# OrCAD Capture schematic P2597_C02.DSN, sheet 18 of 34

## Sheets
18 16_IO Expansion Connector: size Custom
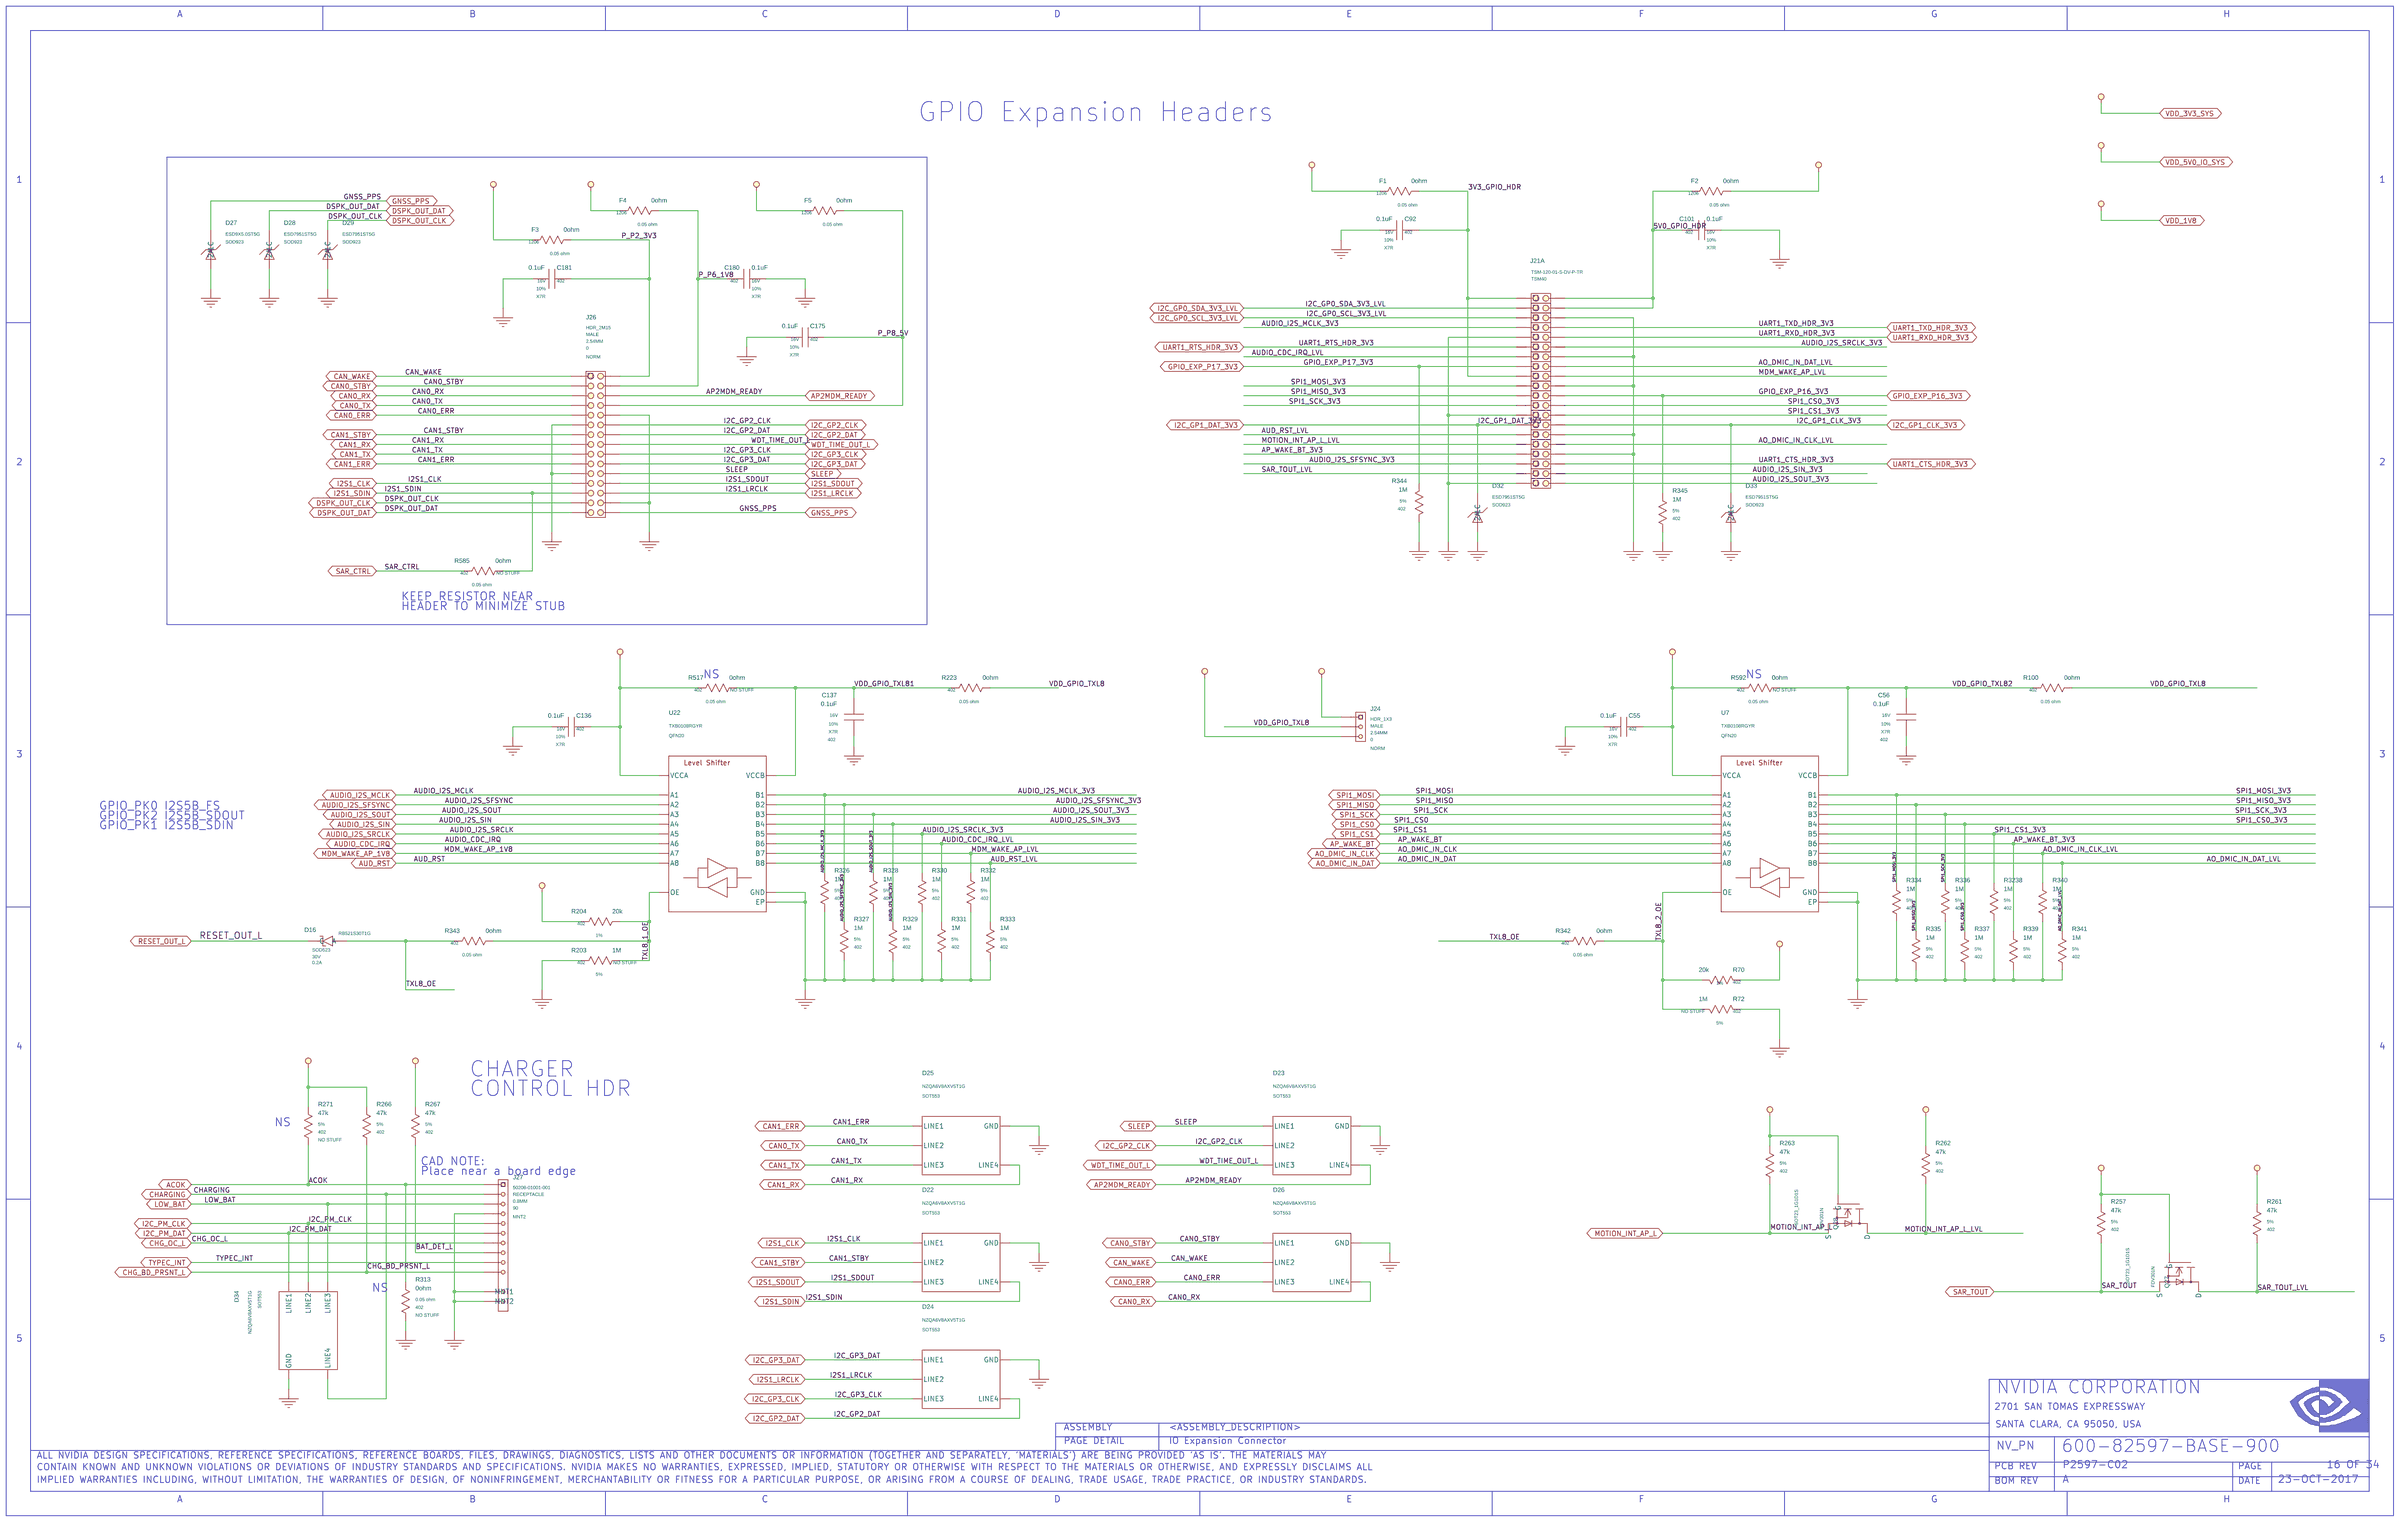
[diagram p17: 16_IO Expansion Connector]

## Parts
C55  0.1uF  [402]
C56  0.1uF  [402]
C92  0.1uF  [402]
C101  0.1uF  [402]
C136  0.1uF  [402]
C137  0.1uF  [402]
C175  0.1uF  [402]
C180  0.1uF  [402]
C181  0.1uF  [402]
D16  D_SCHOTTKY  [DIODE_SMD_SOD523_B]
D22  D_ESD  [SOT553]
D23  D_ESD  [SOT553]
D24  D_ESD  [SOT553]
D25  D_ESD  [SOT553]
D26  D_ESD  [SOT553]
D27  D_ESD  [DIODE_SMD_SOD923]
D28  D_ESD  [DIODE_SMD_SOD923]
D29  D_ESD  [DIODE_SMD_SOD923]
D32  D_ESD  [DIODE_SMD_SOD923]
D33  D_ESD  [DIODE_SMD_SOD923]
D34  D_ESD  [SOT553]
F1  0ohm  [1206]
F2  0ohm  [1206]
F3  0ohm  [1206]
F4  0ohm  [1206]
F5  0ohm  [1206]
J21  HDR_2X20  [CON_TSM_002X020_SMD_ST_M_P025]  (sections A,B,C,D,E,F,G,H,I,J,K,L,M,N,O,P,Q,R,S,T)
J24  HDR_1X3  [CON_HDR_001X003_TH_ST_M_P025_C]
J26  HDR_2X15  [CON_HDR_002X015_TH_ST_M_P025]
J27  HDR_1X10  [CON_MISC_010_SMD_RA_F_P008_WTB]
Q27  Q_FET_N_ENH  [SOT23]
Q28  Q_FET_N_ENH  [SOT23]
R70  20k  [402]
R72  1M  [402]
R100  0ohm  [402]
R203  1M  [402]
R204  20k  [402]
R223  0ohm  [402]
R257  47k  [402]
R261  47k  [402]
R262  47k  [402]
R263  47k  [402]
R266  47k  [402]
R267  47k  [402]
R271  47k  [402]
R313  0ohm  [402]
R326  1M  [402]
R327  1M  [402]
R328  1M  [402]
R329  1M  [402]
R330  1M  [402]
R331  1M  [402]
R332  1M  [402]
R333  1M  [402]
R334  1M  [402]
R335  1M  [402]
R336  1M  [402]
R337  1M  [402]
R339  1M  [402]
R340  1M  [402]
R341  1M  [402]
R342  0ohm  [402]
R343  0ohm  [402]
R344  1M  [402]
R345  1M  [402]
R517  0ohm  [402]
R585  0ohm  [402]
R592  0ohm  [402]
R3238  1M  [402]
U7  U_LEVSHFT_TXB0108  [QFN020R_P050_0045X0035_T031X021_VIAS]
U22  U_LEVSHFT_TXB0108  [QFN020R_P050_0045X0035_T031X021_VIAS]

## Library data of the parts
C55 = C#1: ASSEMBLY: GPIO_HDR; CDS_LIB: discrete; CDS_PART_NAME: C_0402-0.1UF,X7R,10%,16V,036-0014-000; CDS_PHYS_PART_NAME: C_0402-0.1UF,X7R,10%,16V,036-0014-000-0.1UF,036-0014-000; CDS_SEC: 1; CHIPS_PART_NAME: C; DEVICE_TYPENAME: C_0402-01UFX7R1016V036-0014-000-01UF036-0014-000; DRAWING: @P2597_C02_LIB.P2597_C02(SCH_1):PAGE16; ESL: N/A; ESR: N/A; MAT: X7R; MAX_VOLTAGE: 16V; NV_PN: 036-0014-000; PATH: I137; PHYS_PAGE: 16; ROT: 2; SEC: 1; SIGNAL_MODEL: nv_cap; TOL: 10%; VER: 2; XY: (-3850,3900)
C56 = C: ASSEMBLY: GPIO_HDR; CDS_LIB: discrete; CDS_PART_NAME: C_0402-0.1UF,X7R,10%,16V,036-0014-000; CDS_PHYS_PART_NAME: C_0402-0.1UF,X7R,10%,16V,036-0014-000-0.1UF,036-0014-000; CDS_SEC: 1; DEVICE_TYPENAME: C_0402-01UFX7R1016V036-0014-000-01UF036-0014-000; DRAWING: @P2597_C02_LIB.P2597_C02(SCH_1):PAGE16; ESL: N/A; ESR: N/A; MAT: X7R; MAX_VOLTAGE: 16V; NV_PN: 036-0014-000; PATH: I139; PHYS_PAGE: 16; ROT: 2; SEC: 1; SIGNAL_MODEL: nv_cap; TOL: 10%; VER: 1; XY: (-2400,3950)
C92 = C#1: ASSEMBLY: GPIO_HDR; CDS_LIB: discrete; CDS_PART_NAME: C_0402-0.1UF,X7R,10%,16V,036-0014-000; CDS_PHYS_PART_NAME: C_0402-0.1UF,X7R,10%,16V,036-0014-000-0.1UF,036-0014-000; CDS_SEC: 1; CHIPS_PART_NAME: C; DEVICE_TYPENAME: C_0402-01UFX7R1016V036-0014-000-01UF036-0014-000; DRAWING: @P2597_C02_LIB.P2597_C02(SCH_1):PAGE16; ESL: N/A; ESR: N/A; MAT: X7R; MAX_VOLTAGE: 16V; NV_PN: 036-0014-000; PATH: I33; PHYS_PAGE: 16; ROT: 2; SEC: 1; SIGNAL_MODEL: nv_cap; TOL: 10%; VER: 2; XY: (-5000,6450)
C101 = C#1: ASSEMBLY: GPIO_HDR; CDS_LIB: discrete; CDS_PART_NAME: C_0402-0.1UF,X7R,10%,16V,036-0014-000; CDS_PHYS_PART_NAME: C_0402-0.1UF,X7R,10%,16V,036-0014-000-0.1UF,036-0014-000; CDS_SEC: 1; CHIPS_PART_NAME: C; DEVICE_TYPENAME: C_0402-01UFX7R1016V036-0014-000-01UF036-0014-000; DRAWING: @P2597_C02_LIB.P2597_C02(SCH_1):PAGE16; ESL: N/A; ESR: N/A; MAT: X7R; MAX_VOLTAGE: 16V; NV_PN: 036-0014-000; PATH: I41; PHYS_PAGE: 16; ROT: 0; SEC: 1; SIGNAL_MODEL: nv_cap; TOL: 10%; VER: 2; XY: (-3450,6450)
C136 = C#1: ASSEMBLY: GPIO_HDR; CDS_LIB: discrete; CDS_PART_NAME: C_0402-0.1UF,X7R,10%,16V,036-0014-000; CDS_PHYS_PART_NAME: C_0402-0.1UF,X7R,10%,16V,036-0014-000-0.1UF,036-0014-000; CDS_SEC: 1; CHIPS_PART_NAME: C; DEVICE_TYPENAME: C_0402-01UFX7R1016V036-0014-000-01UF036-0014-000; DRAWING: @P2597_C02_LIB.P2597_C02(SCH_1):PAGE16; ESL: N/A; ESR: N/A; MAT: X7R; MAX_VOLTAGE: 16V; NV_PN: 036-0014-000; PATH: I118; PHYS_PAGE: 16; ROT: 2; SEC: 1; SIGNAL_MODEL: nv_cap; TOL: 10%; VER: 2; XY: (-9250,3900)
C137 = C: ASSEMBLY: GPIO_HDR; CDS_LIB: discrete; CDS_PART_NAME: C_0402-0.1UF,X7R,10%,16V,036-0014-000; CDS_PHYS_PART_NAME: C_0402-0.1UF,X7R,10%,16V,036-0014-000-0.1UF,036-0014-000; CDS_SEC: 1; DEVICE_TYPENAME: C_0402-01UFX7R1016V036-0014-000-01UF036-0014-000; DRAWING: @P2597_C02_LIB.P2597_C02(SCH_1):PAGE16; ESL: N/A; ESR: N/A; MAT: X7R; MAX_VOLTAGE: 16V; NV_PN: 036-0014-000; PATH: I120; PHYS_PAGE: 16; ROT: 2; SEC: 1; SIGNAL_MODEL: nv_cap; TOL: 10%; VER: 1; XY: (-7800,3950)
C175 = C#1: ASSEMBLY: GPIO_HDR; CDS_LIB: discrete; CDS_PART_NAME: C_0402-0.1UF,X7R,10%,16V,036-0014-000; CDS_PHYS_PART_NAME: C_0402-0.1UF,X7R,10%,16V,036-0014-000-0.1UF,036-0014-000; CDS_SEC: 1; CHIPS_PART_NAME: C; DEVICE_TYPENAME: C_0402-01UFX7R1016V036-0014-000-01UF036-0014-000; DRAWING: @P2597_C02_LIB.P2597_C02(SCH_1):PAGE16; ESL: N/A; ESR: N/A; MAT: X7R; MAX_VOLTAGE: 16V; NV_PN: 036-0014-000; PATH: I363; PHYS_PAGE: 16; ROT: 2; SEC: 1; SIGNAL_MODEL: nv_cap; TOL: 10%; VER: 2; XY: (-8050,5900)
C180 = C#1: ASSEMBLY: GPIO_HDR; CDS_LIB: discrete; CDS_PART_NAME: C_0402-0.1UF,X7R,10%,16V,036-0014-000; CDS_PHYS_PART_NAME: C_0402-0.1UF,X7R,10%,16V,036-0014-000-0.1UF,036-0014-000; CDS_SEC: 1; CHIPS_PART_NAME: C; DEVICE_TYPENAME: C_0402-01UFX7R1016V036-0014-000-01UF036-0014-000; DRAWING: @P2597_C02_LIB.P2597_C02(SCH_1):PAGE16; ESL: N/A; ESR: N/A; MAT: X7R; MAX_VOLTAGE: 16V; NV_PN: 036-0014-000; PATH: I271; PHYS_PAGE: 16; ROT: 0; SEC: 1; SIGNAL_MODEL: nv_cap; TOL: 10%; VER: 2; XY: (-8350,6200)
C181 = C#1: ASSEMBLY: GPIO_HDR; CDS_LIB: discrete; CDS_PART_NAME: C_0402-0.1UF,X7R,10%,16V,036-0014-000; CDS_PHYS_PART_NAME: C_0402-0.1UF,X7R,10%,16V,036-0014-000-0.1UF,036-0014-000; CDS_SEC: 1; CHIPS_PART_NAME: C; DEVICE_TYPENAME: C_0402-01UFX7R1016V036-0014-000-01UF036-0014-000; DRAWING: @P2597_C02_LIB.P2597_C02(SCH_1):PAGE16; ESL: N/A; ESR: N/A; MAT: X7R; MAX_VOLTAGE: 16V; NV_PN: 036-0014-000; PATH: I266; PHYS_PAGE: 16; ROT: 2; SEC: 1; SIGNAL_MODEL: nv_cap; TOL: 10%; VER: 2; XY: (-9350,6200)
D16 = D_SCHOTTKY: ASSEMBLY: GPIO_HDR; CDS_LIB: discrete; CDS_PART_NAME: D_SCHOTTKY_SOD523-RB521S30T1G,SINGLE,30V,1A,0.5V@0.2A,0.2A,090-0102-000; CDS_PHYS_PART_NAME: D_SCHOTTKY_SOD523-RB521S30T1G,SINGLE,30V,1A,0.5V@0.2A,0.2A,090-0102-000-090-0102-000; CDS_SEC: 1; CONFIGURATION: Single; CONTINUOUS_CURRENT: 0.2A; DEVICE_TYPENAME: D_SCHOTTKY_SOD523-RB521S30T1GSINGLE30V1A05V02A02A090-0102-000-090-0102-000; DRAWING: @P2597_C02_LIB.P2597_C02(SCH_1):PAGE16; FORWARD_VOLTAGE: 0.5V@0.2A; MAX_CURRENT: 1A; MAX_VOLTAGE: 30V; NV_NAME: RB521S30T1G; NV_PN: 090-0102-000; PACK_TYPE: SOD523; PATH: I455; PHYS_PAGE: 16; ROT: 0; SEC: 1; SEC_TYPE: SOD523; VER: 1; XY: (-10500,2800)
D22 = D_ESD#3: ASSEMBLY: GPIO_HDR; BREAKDOWN_VOLTAGE_MIN_TYP: 6.47V; CAPACITANCE_MAX_TYP: 9.5pF; CDS_LIB: discrete; CDS_PART_NAME: D_ESD_SOT553-NZQA6V8AXV5T1G,4 LINE,UNI-DIRECTIONAL,4.3V,1UA,6.47V,13V@1.6A,9.5PF,091-0083-000; CDS_PHYS_PART_NAME: D_ESD_SOT553-NZQA6V8AXV5T1G,4 LINE,UNI-DIRECTIONAL,4.3V,1UA,6.47V,13V@1.6A,9.5PF,091-0083-000-091-0083-000; CDS_SEC: 1; CLAMPING_VOLTAGE: 13V@1.6A; CONFIGURATION: 4 Line; DEVICE_TYPENAME: D_ESD_SOT553-NZQA6V8AXV5T1G4LINEUNI-DIRECTIONAL43V1UA647V13V16A95PF091-0083-000-091-0083-000; DRAWING: @P2597_C02_LIB.P2597_C02(SCH_1):PAGE16; MAX_REVERSE_LEAKAGE_CURRENT: 1uA; MAX_REVERSE_VOLTAGE: 4.3V; NV_NAME: NZQA6V8AXV5T1G; NV_PN: 091-0083-000; PATH: I493; PHYS_PAGE: 16; POLARITY: Uni-Directional; ROT: 0; SEC: 1; VER: 6; XY: (-7250,1150)
D23 = D_ESD#3: ASSEMBLY: GPIO_HDR; BREAKDOWN_VOLTAGE_MIN_TYP: 6.47V; CAPACITANCE_MAX_TYP: 9.5pF; CDS_LIB: discrete; CDS_PART_NAME: D_ESD_SOT553-NZQA6V8AXV5T1G,4 LINE,UNI-DIRECTIONAL,4.3V,1UA,6.47V,13V@1.6A,9.5PF,091-0083-000; CDS_PHYS_PART_NAME: D_ESD_SOT553-NZQA6V8AXV5T1G,4 LINE,UNI-DIRECTIONAL,4.3V,1UA,6.47V,13V@1.6A,9.5PF,091-0083-000-091-0083-000; CDS_SEC: 1; CLAMPING_VOLTAGE: 13V@1.6A; CONFIGURATION: 4 Line; DEVICE_TYPENAME: D_ESD_SOT553-NZQA6V8AXV5T1G4LINEUNI-DIRECTIONAL43V1UA647V13V16A95PF091-0083-000-091-0083-000; DRAWING: @P2597_C02_LIB.P2597_C02(SCH_1):PAGE16; MAX_REVERSE_LEAKAGE_CURRENT: 1uA; MAX_REVERSE_VOLTAGE: 4.3V; NV_NAME: NZQA6V8AXV5T1G; NV_PN: 091-0083-000; PATH: I494; PHYS_PAGE: 16; POLARITY: Uni-Directional; ROT: 0; SEC: 1; VER: 6; XY: (-5450,1750)
D24 = D_ESD#3: ASSEMBLY: GPIO_HDR; BREAKDOWN_VOLTAGE_MIN_TYP: 6.47V; CAPACITANCE_MAX_TYP: 9.5pF; CDS_LIB: discrete; CDS_PART_NAME: D_ESD_SOT553-NZQA6V8AXV5T1G,4 LINE,UNI-DIRECTIONAL,4.3V,1UA,6.47V,13V@1.6A,9.5PF,091-0083-000; CDS_PHYS_PART_NAME: D_ESD_SOT553-NZQA6V8AXV5T1G,4 LINE,UNI-DIRECTIONAL,4.3V,1UA,6.47V,13V@1.6A,9.5PF,091-0083-000-091-0083-000; CDS_SEC: 1; CLAMPING_VOLTAGE: 13V@1.6A; CONFIGURATION: 4 Line; DEVICE_TYPENAME: D_ESD_SOT553-NZQA6V8AXV5T1G4LINEUNI-DIRECTIONAL43V1UA647V13V16A95PF091-0083-000-091-0083-000; DRAWING: @P2597_C02_LIB.P2597_C02(SCH_1):PAGE16; MAX_REVERSE_LEAKAGE_CURRENT: 1uA; MAX_REVERSE_VOLTAGE: 4.3V; NV_NAME: NZQA6V8AXV5T1G; NV_PN: 091-0083-000; PATH: I492; PHYS_PAGE: 16; POLARITY: Uni-Directional; ROT: 0; SEC: 1; VER: 6; XY: (-7250,550)
D25 = D_ESD#3: ASSEMBLY: GPIO_HDR; BREAKDOWN_VOLTAGE_MIN_TYP: 6.47V; CAPACITANCE_MAX_TYP: 9.5pF; CDS_LIB: discrete; CDS_PART_NAME: D_ESD_SOT553-NZQA6V8AXV5T1G,4 LINE,UNI-DIRECTIONAL,4.3V,1UA,6.47V,13V@1.6A,9.5PF,091-0083-000; CDS_PHYS_PART_NAME: D_ESD_SOT553-NZQA6V8AXV5T1G,4 LINE,UNI-DIRECTIONAL,4.3V,1UA,6.47V,13V@1.6A,9.5PF,091-0083-000-091-0083-000; CDS_SEC: 1; CLAMPING_VOLTAGE: 13V@1.6A; CONFIGURATION: 4 Line; DEVICE_TYPENAME: D_ESD_SOT553-NZQA6V8AXV5T1G4LINEUNI-DIRECTIONAL43V1UA647V13V16A95PF091-0083-000-091-0083-000; DRAWING: @P2597_C02_LIB.P2597_C02(SCH_1):PAGE16; MAX_REVERSE_LEAKAGE_CURRENT: 1uA; MAX_REVERSE_VOLTAGE: 4.3V; NV_NAME: NZQA6V8AXV5T1G; NV_PN: 091-0083-000; PATH: I496; PHYS_PAGE: 16; POLARITY: Uni-Directional; ROT: 0; SEC: 1; VER: 6; XY: (-7250,1750)
D26 = D_ESD#3: ASSEMBLY: GPIO_HDR; BREAKDOWN_VOLTAGE_MIN_TYP: 6.47V; CAPACITANCE_MAX_TYP: 9.5pF; CDS_LIB: discrete; CDS_PART_NAME: D_ESD_SOT553-NZQA6V8AXV5T1G,4 LINE,UNI-DIRECTIONAL,4.3V,1UA,6.47V,13V@1.6A,9.5PF,091-0083-000; CDS_PHYS_PART_NAME: D_ESD_SOT553-NZQA6V8AXV5T1G,4 LINE,UNI-DIRECTIONAL,4.3V,1UA,6.47V,13V@1.6A,9.5PF,091-0083-000-091-0083-000; CDS_SEC: 1; CLAMPING_VOLTAGE: 13V@1.6A; CONFIGURATION: 4 Line; DEVICE_TYPENAME: D_ESD_SOT553-NZQA6V8AXV5T1G4LINEUNI-DIRECTIONAL43V1UA647V13V16A95PF091-0083-000-091-0083-000; DRAWING: @P2597_C02_LIB.P2597_C02(SCH_1):PAGE16; MAX_REVERSE_LEAKAGE_CURRENT: 1uA; MAX_REVERSE_VOLTAGE: 4.3V; NV_NAME: NZQA6V8AXV5T1G; NV_PN: 091-0083-000; PATH: I499; PHYS_PAGE: 16; POLARITY: Uni-Directional; ROT: 0; SEC: 1; VER: 6; XY: (-5450,1150)
D27 = D_ESD#1: ASSEMBLY: GPIO_HDR; BREAKDOWN_VOLTAGE_MIN_TYP: 6.2V; CAPACITANCE_MAX_TYP: 65pF; CDS_LIB: discrete; CDS_PART_NAME: D_ESD_SOD923-ESD9X5.0ST5G,1 LINE,UNI-DIRECTIONAL,5V,1UA,6.2V,12.3V@8.7A,65PF,090-0134-000; CDS_PHYS_PART_NAME: D_ESD_SOD923-ESD9X5.0ST5G,1 LINE,UNI-DIRECTIONAL,5V,1UA,6.2V,12.3V@8.7A,65PF,090-0134-000-090-0134-000; CDS_SEC: 1; CLAMPING_VOLTAGE: 12.3V@8.7A; CONFIGURATION: 1 Line; CONTINUOUS_CURRENT: -1A; DEVICE_TYPENAME: D_ESD_SOD923-ESD9X50ST5G1LINEUNI-DIRECTIONAL5V1UA62V123V87A65PF090-0134-000-090-0134-000; DRAWING: @P2597_C02_LIB.P2597_C02(SCH_1):PAGE16; FORWARD_VOLTAGE: [ ]@-9.999A; MAX_CURRENT: [ ]; MAX_REVERSE_LEAKAGE_CURRENT: 1uA; MAX_REVERSE_VOLTAGE: 5V; MAX_VOLTAGE: 5V; NV_NAME: ESD9X5.0ST5G; NV_PN: 090-0134-000; PACK_TYPE: SOD923; PATH: I533; PHYS_PAGE: 16; POLARITY: Uni-Directional; ROT: 0; SEC: 1; VER: 5; XY: (-11100,6350)
D28 = D_ESD#1: ASSEMBLY: GPIO_HDR; BREAKDOWN_VOLTAGE_MIN_TYP: 5.4V; CAPACITANCE_MAX_TYP: 0.9pF; CDS_LIB: discrete; CDS_PART_NAME: D_ESD_SOD923-ESD7951ST5G,1 LINE,BI-DIRECTIONAL,5V,1UA,5.4V,12.9V@1A,0.9PF,091-0074-000; CDS_PHYS_PART_NAME: D_ESD_SOD923-ESD7951ST5G,1 LINE,BI-DIRECTIONAL,5V,1UA,5.4V,12.9V@1A,0.9PF,091-0074-000-091-0074-000; CDS_SEC: 1; CLAMPING_VOLTAGE: 12.9V@1A; CONFIGURATION: 1 Line; CONTINUOUS_CURRENT: -1A; DEVICE_TYPENAME: D_ESD_SOD923-ESD7951ST5G1LINEBI-DIRECTIONAL5V1UA54V129V1A09PF091-0074-000-091-0074-000; DRAWING: @P2597_C02_LIB.P2597_C02(SCH_1):PAGE16; FORWARD_VOLTAGE: [ ]@-9.999A; MAX_CURRENT: [ ]; MAX_REVERSE_LEAKAGE_CURRENT: 1uA; MAX_REVERSE_VOLTAGE: 5V; MAX_VOLTAGE: 5V; NV_NAME: ESD7951ST5G; NV_PN: 091-0074-000; PACK_TYPE: SOD923; PATH: I500; PHYS_PAGE: 16; POLARITY: Bi-Directional; ROT: 0; SEC: 1; VER: 5; XY: (-10800,6350)
D29 = D_ESD#1: ASSEMBLY: GPIO_HDR; BREAKDOWN_VOLTAGE_MIN_TYP: 5.4V; CAPACITANCE_MAX_TYP: 0.9pF; CDS_LIB: discrete; CDS_PART_NAME: D_ESD_SOD923-ESD7951ST5G,1 LINE,BI-DIRECTIONAL,5V,1UA,5.4V,12.9V@1A,0.9PF,091-0074-000; CDS_PHYS_PART_NAME: D_ESD_SOD923-ESD7951ST5G,1 LINE,BI-DIRECTIONAL,5V,1UA,5.4V,12.9V@1A,0.9PF,091-0074-000-091-0074-000; CDS_SEC: 1; CLAMPING_VOLTAGE: 12.9V@1A; CONFIGURATION: 1 Line; CONTINUOUS_CURRENT: -1A; DEVICE_TYPENAME: D_ESD_SOD923-ESD7951ST5G1LINEBI-DIRECTIONAL5V1UA54V129V1A09PF091-0074-000-091-0074-000; DRAWING: @P2597_C02_LIB.P2597_C02(SCH_1):PAGE16; FORWARD_VOLTAGE: [ ]@-9.999A; MAX_CURRENT: [ ]; MAX_REVERSE_LEAKAGE_CURRENT: 1uA; MAX_REVERSE_VOLTAGE: 5V; MAX_VOLTAGE: 5V; NV_NAME: ESD7951ST5G; NV_PN: 091-0074-000; PACK_TYPE: SOD923; PATH: I502; PHYS_PAGE: 16; POLARITY: Bi-Directional; ROT: 0; SEC: 1; VER: 5; XY: (-10500,6350)
D32 = D_ESD#1: ASSEMBLY: GPIO_HDR; BREAKDOWN_VOLTAGE_MIN_TYP: 5.4V; CAPACITANCE_MAX_TYP: 0.9pF; CDS_LIB: discrete; CDS_PART_NAME: D_ESD_SOD923-ESD7951ST5G,1 LINE,BI-DIRECTIONAL,5V,1UA,5.4V,12.9V@1A,0.9PF,091-0074-000; CDS_PHYS_PART_NAME: D_ESD_SOD923-ESD7951ST5G,1 LINE,BI-DIRECTIONAL,5V,1UA,5.4V,12.9V@1A,0.9PF,091-0074-000-091-0074-000; CDS_SEC: 1; CLAMPING_VOLTAGE: 12.9V@1A; CONFIGURATION: 1 Line; CONTINUOUS_CURRENT: -1A; DEVICE_TYPENAME: D_ESD_SOD923-ESD7951ST5G1LINEBI-DIRECTIONAL5V1UA54V129V1A09PF091-0074-000-091-0074-000; DRAWING: @P2597_C02_LIB.P2597_C02(SCH_1):PAGE16; FORWARD_VOLTAGE: [ ]@-9.999A; MAX_CURRENT: [ ]; MAX_REVERSE_LEAKAGE_CURRENT: 1uA; MAX_REVERSE_VOLTAGE: 5V; MAX_VOLTAGE: 5V; NV_NAME: ESD7951ST5G; NV_PN: 091-0074-000; PACK_TYPE: SOD923; PATH: I506; PHYS_PAGE: 16; POLARITY: Bi-Directional; ROT: 0; SEC: 1; SEC_TYPE: SOD923; VER: 5; XY: (-4600,5000)
D33 = D_ESD#1: ASSEMBLY: GPIO_HDR; BREAKDOWN_VOLTAGE_MIN_TYP: 5.4V; CAPACITANCE_MAX_TYP: 0.9pF; CDS_LIB: discrete; CDS_PART_NAME: D_ESD_SOD923-ESD7951ST5G,1 LINE,BI-DIRECTIONAL,5V,1UA,5.4V,12.9V@1A,0.9PF,091-0074-000; CDS_PHYS_PART_NAME: D_ESD_SOD923-ESD7951ST5G,1 LINE,BI-DIRECTIONAL,5V,1UA,5.4V,12.9V@1A,0.9PF,091-0074-000-091-0074-000; CDS_SEC: 1; CLAMPING_VOLTAGE: 12.9V@1A; CONFIGURATION: 1 Line; CONTINUOUS_CURRENT: -1A; DEVICE_TYPENAME: D_ESD_SOD923-ESD7951ST5G1LINEBI-DIRECTIONAL5V1UA54V129V1A09PF091-0074-000-091-0074-000; DRAWING: @P2597_C02_LIB.P2597_C02(SCH_1):PAGE16; FORWARD_VOLTAGE: [ ]@-9.999A; MAX_CURRENT: [ ]; MAX_REVERSE_LEAKAGE_CURRENT: 1uA; MAX_REVERSE_VOLTAGE: 5V; MAX_VOLTAGE: 5V; NV_NAME: ESD7951ST5G; NV_PN: 091-0074-000; PACK_TYPE: SOD923; PATH: I504; PHYS_PAGE: 16; POLARITY: Bi-Directional; ROT: 0; SEC: 1; SEC_TYPE: SOD923; VER: 5; XY: (-3300,5000)
D34 = D_ESD#3: ASSEMBLY: GPIO_HDR; BREAKDOWN_VOLTAGE_MIN_TYP: 6.47V; CAPACITANCE_MAX_TYP: 9.5pF; CDS_LIB: discrete; CDS_PART_NAME: D_ESD_SOT553-NZQA6V8AXV5T1G,4 LINE,UNI-DIRECTIONAL,4.3V,1UA,6.47V,13V@1.6A,9.5PF,091-0083-000; CDS_PHYS_PART_NAME: D_ESD_SOT553-NZQA6V8AXV5T1G,4 LINE,UNI-DIRECTIONAL,4.3V,1UA,6.47V,13V@1.6A,9.5PF,091-0083-000-091-0083-000; CDS_SEC: 1; CLAMPING_VOLTAGE: 13V@1.6A; CONFIGURATION: 4 Line; DEVICE_TYPENAME: D_ESD_SOT553-NZQA6V8AXV5T1G4LINEUNI-DIRECTIONAL43V1UA647V13V16A95PF091-0083-000-091-0083-000; DRAWING: @P2597_C02_LIB.P2597_C02(SCH_1):PAGE16; MAX_REVERSE_LEAKAGE_CURRENT: 1uA; MAX_REVERSE_VOLTAGE: 4.3V; NV_NAME: NZQA6V8AXV5T1G; NV_PN: 091-0083-000; PATH: I508; PHYS_PAGE: 16; POLARITY: Uni-Directional; ROT: 3; SEC: 1; VER: 6; XY: (-10600,800)
F1 = R: ASSEMBLY: GPIO_HDR; CDS_LIB: discrete; CDS_PART_NAME: R_1206-0OHM,0.05 OHM,0.25W,195-1635-000; CDS_PHYS_PART_NAME: R_1206-0OHM,0.05 OHM,0.25W,195-1635-000-0OHM,195-1635-000; CDS_SEC: 1; DEVICE_TYPENAME: R_1206-0OHM005OHM025W195-1635-000-0OHM195-1635-000; DRAWING: @P2597_C02_LIB.P2597_C02(SCH_1):PAGE16; MAX_WATTAGE: 0.25W; NV_PN: 195-1635-000; PATH: I369; PHYS_PAGE: 16; ROT: 0; SEC: 1; SIGNAL_MODEL: nv_res; TOL: 0.05 ohm; VER: 1; XY: (-5000,6650)
F2 = R: ASSEMBLY: GPIO_HDR; CDS_LIB: discrete; CDS_PART_NAME: R_1206-0OHM,0.05 OHM,0.25W,195-1635-000; CDS_PHYS_PART_NAME: R_1206-0OHM,0.05 OHM,0.25W,195-1635-000-0OHM,195-1635-000; CDS_SEC: 1; DEVICE_TYPENAME: R_1206-0OHM005OHM025W195-1635-000-0OHM195-1635-000; DRAWING: @P2597_C02_LIB.P2597_C02(SCH_1):PAGE16; MAX_WATTAGE: 0.25W; NV_PN: 195-1635-000; PATH: I370; PHYS_PAGE: 16; ROT: 0; SEC: 1; SIGNAL_MODEL: nv_res; TOL: 0.05 ohm; VER: 1; XY: (-3400,6650)
F3 = R: ASSEMBLY: GPIO_HDR; CDS_LIB: discrete; CDS_PART_NAME: R_1206-0OHM,0.05 OHM,0.25W,195-1635-000; CDS_PHYS_PART_NAME: R_1206-0OHM,0.05 OHM,0.25W,195-1635-000-0OHM,195-1635-000; CDS_SEC: 1; DEVICE_TYPENAME: R_1206-0OHM005OHM025W195-1635-000-0OHM195-1635-000; DRAWING: @P2597_C02_LIB.P2597_C02(SCH_1):PAGE16; MAX_WATTAGE: 0.25W; NV_PN: 195-1635-000; PATH: I406; PHYS_PAGE: 16; ROT: 0; SEC: 1; SIGNAL_MODEL: nv_res; TOL: 0.05 ohm; VER: 1; XY: (-9350,6400)
F4 = R: ASSEMBLY: GPIO_HDR; CDS_LIB: discrete; CDS_PART_NAME: R_1206-0OHM,0.05 OHM,0.25W,195-1635-000; CDS_PHYS_PART_NAME: R_1206-0OHM,0.05 OHM,0.25W,195-1635-000-0OHM,195-1635-000; CDS_SEC: 1; DEVICE_TYPENAME: R_1206-0OHM005OHM025W195-1635-000-0OHM195-1635-000; DRAWING: @P2597_C02_LIB.P2597_C02(SCH_1):PAGE16; MAX_WATTAGE: 0.25W; NV_PN: 195-1635-000; PATH: I409; PHYS_PAGE: 16; ROT: 0; SEC: 1; SIGNAL_MODEL: nv_res; TOL: 0.05 ohm; VER: 1; XY: (-8900,6550)
F5 = R: ASSEMBLY: GPIO_HDR; CDS_LIB: discrete; CDS_PART_NAME: R_1206-0OHM,0.05 OHM,0.25W,195-1635-000; CDS_PHYS_PART_NAME: R_1206-0OHM,0.05 OHM,0.25W,195-1635-000-0OHM,195-1635-000; CDS_SEC: 1; DEVICE_TYPENAME: R_1206-0OHM005OHM025W195-1635-000-0OHM195-1635-000; DRAWING: @P2597_C02_LIB.P2597_C02(SCH_1):PAGE16; MAX_WATTAGE: 0.25W; NV_PN: 195-1635-000; PATH: I410; PHYS_PAGE: 16; ROT: 0; SEC: 1; SIGNAL_MODEL: nv_res; TOL: 0.05 ohm; VER: 1; XY: (-7950,6550)
J21 = HDR_2X20: ANGLE: 0; ASSEMBLY: GPIO_HDR; CDS_LIB: electro_mechanic; CDS_PART_NAME: HDR_2X20_TSM40-TSM-120-01-S-DV-P-TR,MALE,2.54MM,0,YES,NO,NO,NA,NA,080-1348-000; CDS_PHYS_PART_NAME: HDR_2X20_TSM40-TSM-120-01-S-DV-P-TR,MALE,2.54MM,0,YES,NO,NO,NA,NA,080-1348-000-080-1348-000; CDS_SEC: 17; DEVICE_TYPENAME: HDR_2X20_TSM40-TSM-120-01-S-DV-P-TRMALE254MM0YESNONONANA080-1348-000-080-1348-000; DRAWING: @P2597_C02_LIB.P2597_C02(SCH_1):PAGE16; GENDER: MALE; LATCHING: NO; MAX_CURRENT: NA; MAX_VOLTAGE: NA; NV_NAME: TSM-120-01-S-DV-P-TR; NV_PN: 080-1348-000; PACK_TYPE: TSM40; PATH: I202; PHYS_PAGE: 16; PITCH: 2.54MM; REFLOW: YES; ROT: 0; SEC: 17; SEC_TYPE: TSM40; SHROUDED: NO; VER: 3; XY: (-4300,5300)
J24 = HDR_1X3: ANGLE: 0; ASSEMBLY: GPIO_HDR; CDS_LIB: electro_mechanic; CDS_PART_NAME: HDR_1X3_NORM-HDR_1X3,MALE,2.54MM,0,YES,NO,NO,500V,3A,074-0011-000; CDS_PHYS_PART_NAME: HDR_1X3_NORM-HDR_1X3,MALE,2.54MM,0,YES,NO,NO,500V,3A,074-0011-000-074-0011-000; CDS_SEC: 1; DEVICE_TYPENAME: HDR_1X3_NORM-HDR_1X3MALE254MM0YESNONO500V3A074-0011-000-074-0011-000; DRAWING: @P2597_C02_LIB.P2597_C02(SCH_1):PAGE16; GENDER: MALE; LATCHING: NO; MAX_CURRENT: 3A; MAX_VOLTAGE: 500V; NV_PN: 074-0011-000; PACK_TYPE: NORM; PATH: I174; PHYS_PAGE: 16; PITCH: 2.54MM; REFLOW: YES; ROT: 0; SEC: 1; SEC_TYPE: NORM; SHROUDED: NO; VER: 1; XY: (-5200,3950)
J26 = HDR_2X15: ANGLE: 0; ASSEMBLY: GPIO_HDR; CDS_LIB: electro_mechanic; CDS_PART_NAME: HDR_2X15_NORM-HDR_2M15,MALE,2.54MM,0,NO,NO,NO,500V,3A,074-0110-000; CDS_PHYS_PART_NAME: HDR_2X15_NORM-HDR_2M15,MALE,2.54MM,0,NO,NO,NO,500V,3A,074-0110-000-074-0110-000; CDS_SEC: 1; DEVICE_TYPENAME: HDR_2X15_NORM-HDR_2M15MALE254MM0NONONO500V3A074-0110-000-074-0110-000; DRAWING: @P2597_C02_LIB.P2597_C02(SCH_1):PAGE16; GENDER: MALE; LATCHING: NO; MAX_CURRENT: 3A; MAX_VOLTAGE: 500V; NV_NAME: HDR_2M15; NV_PN: 074-0110-000; PACK_TYPE: NORM; PATH: I327; PHYS_PAGE: 16; PITCH: 2.54MM; REFLOW: NO; ROT: 0; SEC: 1; SEC_TYPE: NORM; SHROUDED: NO; VER: 1; XY: (-9150,5700)
J27 = HDR_1X10: ANGLE: 90; ASSEMBLY: GPIO_HDR; CDS_LIB: electro_mechanic; CDS_PART_NAME: HDR_1X10_MNT2-50208-01001-001,RECEPTACLE,0.8MM,90,YES,N/A,NO,N/A,N/A,080-0791-000; CDS_PHYS_PART_NAME: HDR_1X10_MNT2-50208-01001-001,RECEPTACLE,0.8MM,90,YES,N/A,NO,N/A,N/A,080-0791-000-080-0791-000; CDS_SEC: 1; DEVICE_TYPENAME: HDR_1X10_MNT2-50208-01001-001RECEPTACLE08MM90YESNANONANA080-0791-000-080-0791-000; DRAWING: @P2597_C02_LIB.P2597_C02(SCH_1):PAGE16; GENDER: RECEPTACLE; LATCHING: NO; MAX_CURRENT: N/A; MAX_VOLTAGE: N/A; NV_NAME: 50208-01001-001; NV_PN: 080-0791-000; PACK_TYPE: MNT2; PATH: I350; PHYS_PAGE: 16; PITCH: 0.8MM; REFLOW: YES; ROT: 0; SEC: 1; SEC_TYPE: MNT2; SHROUDED: N/A; VER: 3; XY: (-9600,1550)
Q27 = Q_FET_N_ENH#2: ASSEMBLY: GPIO_HDR; CDS_LIB: discrete; CDS_PART_NAME: Q_FET_N_ENH_SOT23_1G1D1S-FDV301N,25V,-1000MOHM@10V / 4000MOHM@4.5V / -1000MOHM@2.5V,0.22A,0.5A,8V,0.35W,[ ]@10V / [ ]@4.5V / [A; CDS_PHYS_PART_NAME: Q_FET_N_ENH_SOT23_1G1D1S-FDV301N,25V,-1000MOHM@10V / 4000MOHM@4.5V / -1000MOHM@2.5V,0.22A,0.5A,8V,0.35W,[ ]@10V / [ ]@4.5V / [B; CDS_SEC: 1; CONTINUOUS_CURRENT: 0.22A; CaptureCellPackProp: Q_FET_N_ENH__sym_2##2; DEVICE_TYPENAME: Q_FET_N_ENH_SOT23_1G1D1S-FDV301N25V-1000MOHM10V4000MOHM45V-1000MOHM25V022A05A8V035W10V45VB; DRAWING: @P2597_C02_LIB.P2597_C02(SCH_1):PAGE16; IMPLEMENTATION_TYPE: Pspice Model; MAX_CURRENT: 0.5A; MAX_VOLTAGE: 25V; MAX_WATTAGE: 0.35W; NV_NAME: FDV301N; NV_PN: 300-0494-000; PACK_TYPE: SOT23_1G1D1S; PATH: I391; PHYS_PAGE: 16; PSPICETEMPLATE: X^@REFDES %D %G %S @NV_PN; Q_G: [ ]@10V / [ ]@4.5V / [ ]@2.5V; ROT: 5; R_DS_ON: -1000mohm@10V / 4000mohm@4.5V / -1000mohm@2.5V; SEC: 1; SEC_TYPE: SOT23_1G1D1S; VER: 2; V_BE_GS: 8V; XY: (-1000,1100)
Q28 = Q_FET_N_ENH#2: ASSEMBLY: GPIO_HDR; CDS_LIB: discrete; CDS_PART_NAME: Q_FET_N_ENH_SOT23_1G1D1S-FDV301N,25V,-1000MOHM@10V / 4000MOHM@4.5V / -1000MOHM@2.5V,0.22A,0.5A,8V,0.35W,[ ]@10V / [ ]@4.5V / [A; CDS_PHYS_PART_NAME: Q_FET_N_ENH_SOT23_1G1D1S-FDV301N,25V,-1000MOHM@10V / 4000MOHM@4.5V / -1000MOHM@2.5V,0.22A,0.5A,8V,0.35W,[ ]@10V / [ ]@4.5V / [B; CDS_SEC: 1; CONTINUOUS_CURRENT: 0.22A; CaptureCellPackProp: Q_FET_N_ENH__sym_2##2; DEVICE_TYPENAME: Q_FET_N_ENH_SOT23_1G1D1S-FDV301N25V-1000MOHM10V4000MOHM45V-1000MOHM25V022A05A8V035W10V45VB; DRAWING: @P2597_C02_LIB.P2597_C02(SCH_1):PAGE16; IMPLEMENTATION_TYPE: Pspice Model; MAX_CURRENT: 0.5A; MAX_VOLTAGE: 25V; MAX_WATTAGE: 0.35W; NV_NAME: FDV301N; NV_PN: 300-0494-000; PACK_TYPE: SOT23_1G1D1S; PATH: I380; PHYS_PAGE: 16; PSPICETEMPLATE: X^@REFDES %D %G %S @NV_PN; Q_G: [ ]@10V / [ ]@4.5V / [ ]@2.5V; ROT: 5; R_DS_ON: -1000mohm@10V / 4000mohm@4.5V / -1000mohm@2.5V; SEC: 1; SEC_TYPE: SOT23_1G1D1S; VER: 2; V_BE_GS: 8V; XY: (-2700,1400)
R70 = R: ASSEMBLY: GPIO_HDR; CDS_LIB: discrete; CDS_PART_NAME: R_0402-20K,1 %,62.5MW,195-0150-000; CDS_PHYS_PART_NAME: R_0402-20K,1 %,62.5MW,195-0150-000-195-0150-000,20K; CDS_SEC: 1; DEVICE_TYPENAME: R_0402-20K1625MW195-0150-000-195-0150-00020K; DRAWING: @P2597_C02_LIB.P2597_C02(SCH_1):PAGE16; MAX_WATTAGE: 62.5mW; NV_PN: 195-0150-000; PATH: I160; PHYS_PAGE: 16; ROT: 2; SEC: 1; SIGNAL_MODEL: nv_res; TOL: 1%; VER: 1; XY: (-3350,2600)
R72 = R: ASSEMBLY: GPIO_HDR; CDS_LIB: discrete; CDS_PART_NAME: R_0402-1M,5 %,62.5MW,195-0488-000; CDS_PHYS_PART_NAME: R_0402-1M,5 %,62.5MW,195-0488-000-195-0488-000,1M; CDS_SEC: 1; DEVICE_TYPENAME: R_0402-1M5625MW195-0488-000-195-0488-0001M; DRAWING: @P2597_C02_LIB.P2597_C02(SCH_1):PAGE16; MAX_WATTAGE: 62.5mW; NV_PN: 195-0488-000; PATH: I172; PHYS_PAGE: 16; ROT: 2; SEC: 1; SIGNAL_MODEL: nv_res; SKU: NO STUFF; TOL: 5%; VER: 1; XY: (-3350,2450)
R100 = R: ASSEMBLY: GPIO_HDR; CDS_LIB: discrete; CDS_PART_NAME: R_0402-0OHM,0.05 OHM,62.5MW,195-2655-000; CDS_PHYS_PART_NAME: R_0402-0OHM,0.05 OHM,62.5MW,195-2655-000-0OHM,195-2655-000; CDS_SEC: 1; DEVICE_TYPENAME: R_0402-0OHM005OHM625MW195-2655-000-0OHM195-2655-000; DRAWING: @P2597_C02_LIB.P2597_C02(SCH_1):PAGE16; MAX_WATTAGE: 62.5mW; NO_XNET_CONNECTION: 1; NV_PN: 195-2655-000; PATH: I368; PHYS_PAGE: 16; ROT: 0; SEC: 1; SIGNAL_MODEL: nv_res; TOL: 0.05 ohm; VER: 1; XY: (-1650,4100)
R203 = R: ASSEMBLY: GPIO_HDR; CDS_LIB: discrete; CDS_PART_NAME: R_0402-1M,5 %,62.5MW,195-0488-000; CDS_PHYS_PART_NAME: R_0402-1M,5 %,62.5MW,195-0488-000-195-0488-000,1M; CDS_SEC: 1; DEVICE_TYPENAME: R_0402-1M5625MW195-0488-000-195-0488-0001M; DRAWING: @P2597_C02_LIB.P2597_C02(SCH_1):PAGE16; MAX_WATTAGE: 62.5mW; NV_PN: 195-0488-000; PATH: I170; PHYS_PAGE: 16; ROT: 0; SEC: 1; SIGNAL_MODEL: nv_res; SKU: NO STUFF; TOL: 5%; VER: 1; XY: (-9100,2700)
R204 = R: ASSEMBLY: GPIO_HDR; CDS_LIB: discrete; CDS_PART_NAME: R_0402-20K,1 %,62.5MW,195-0150-000; CDS_PHYS_PART_NAME: R_0402-20K,1 %,62.5MW,195-0150-000-195-0150-000,20K; CDS_SEC: 1; DEVICE_TYPENAME: R_0402-20K1625MW195-0150-000-195-0150-00020K; DRAWING: @P2597_C02_LIB.P2597_C02(SCH_1):PAGE16; MAX_WATTAGE: 62.5mW; NV_PN: 195-0150-000; PATH: I159; PHYS_PAGE: 16; ROT: 0; SEC: 1; SIGNAL_MODEL: nv_res; TOL: 1%; VER: 1; XY: (-9100,2900)
R223 = R: ASSEMBLY: GPIO_HDR; CDS_LIB: discrete; CDS_PART_NAME: R_0402-0OHM,0.05 OHM,62.5MW,195-2655-000; CDS_PHYS_PART_NAME: R_0402-0OHM,0.05 OHM,62.5MW,195-2655-000-0OHM,195-2655-000; CDS_SEC: 1; DEVICE_TYPENAME: R_0402-0OHM005OHM625MW195-2655-000-0OHM195-2655-000; DRAWING: @P2597_C02_LIB.P2597_C02(SCH_1):PAGE16; MAX_WATTAGE: 62.5mW; NO_XNET_CONNECTION: 1; NV_PN: 195-2655-000; PATH: I367; PHYS_PAGE: 16; ROT: 0; SEC: 1; SIGNAL_MODEL: nv_res; TOL: 0.05 ohm; VER: 1; XY: (-7200,4100)
R257 = R#1: ASSEMBLY: GPIO_HDR; CDS_LIB: discrete; CDS_PART_NAME: R_0402-47K,5 %,62.5MW,195-0599-000; CDS_PHYS_PART_NAME: R_0402-47K,5 %,62.5MW,195-0599-000-195-0599-000,47K; CDS_SEC: 1; CHIPS_PART_NAME: R; DEVICE_TYPENAME: R_0402-47K5625MW195-0599-000-195-0599-00047K; DRAWING: @P2597_C02_LIB.P2597_C02(SCH_1):PAGE16; MAX_WATTAGE: 62.5mW; NV_PN: 195-0599-000; PATH: I392; PHYS_PAGE: 16; ROT: 0; SEC: 1; SIGNAL_MODEL: nv_res; TOL: 5%; VER: 2; XY: (-1400,1350)
R261 = R#1: ASSEMBLY: GPIO_HDR; CDS_LIB: discrete; CDS_PART_NAME: R_0402-47K,5 %,62.5MW,195-0599-000; CDS_PHYS_PART_NAME: R_0402-47K,5 %,62.5MW,195-0599-000-195-0599-000,47K; CDS_SEC: 1; CHIPS_PART_NAME: R; DEVICE_TYPENAME: R_0402-47K5625MW195-0599-000-195-0599-00047K; DRAWING: @P2597_C02_LIB.P2597_C02(SCH_1):PAGE16; MAX_WATTAGE: 62.5mW; NV_PN: 195-0599-000; PATH: I390; PHYS_PAGE: 16; ROT: 0; SEC: 1; SIGNAL_MODEL: nv_res; TOL: 5%; VER: 2; XY: (-600,1350)
R262 = R#1: ASSEMBLY: GPIO_HDR; CDS_LIB: discrete; CDS_PART_NAME: R_0402-47K,5 %,62.5MW,195-0599-000; CDS_PHYS_PART_NAME: R_0402-47K,5 %,62.5MW,195-0599-000-195-0599-000,47K; CDS_SEC: 1; CHIPS_PART_NAME: R; DEVICE_TYPENAME: R_0402-47K5625MW195-0599-000-195-0599-00047K; DRAWING: @P2597_C02_LIB.P2597_C02(SCH_1):PAGE16; MAX_WATTAGE: 62.5mW; NV_PN: 195-0599-000; PATH: I383; PHYS_PAGE: 16; ROT: 0; SEC: 1; SIGNAL_MODEL: nv_res; TOL: 5%; VER: 2; XY: (-2300,1650)
R263 = R#1: ASSEMBLY: GPIO_HDR; CDS_LIB: discrete; CDS_PART_NAME: R_0402-47K,5 %,62.5MW,195-0599-000; CDS_PHYS_PART_NAME: R_0402-47K,5 %,62.5MW,195-0599-000-195-0599-000,47K; CDS_SEC: 1; CHIPS_PART_NAME: R; DEVICE_TYPENAME: R_0402-47K5625MW195-0599-000-195-0599-00047K; DRAWING: @P2597_C02_LIB.P2597_C02(SCH_1):PAGE16; MAX_WATTAGE: 62.5mW; NV_PN: 195-0599-000; PATH: I381; PHYS_PAGE: 16; ROT: 0; SEC: 1; SIGNAL_MODEL: nv_res; TOL: 5%; VER: 2; XY: (-3100,1650)
R266 = R#1: ASSEMBLY: GPIO_HDR; CDS_LIB: discrete; CDS_PART_NAME: R_0402-47K,5 %,62.5MW,195-0599-000; CDS_PHYS_PART_NAME: R_0402-47K,5 %,62.5MW,195-0599-000-195-0599-000,47K; CDS_SEC: 1; CHIPS_PART_NAME: R; DEVICE_TYPENAME: R_0402-47K5625MW195-0599-000-195-0599-00047K; DRAWING: @P2597_C02_LIB.P2597_C02(SCH_1):PAGE16; MAX_WATTAGE: 62.5mW; NV_PN: 195-0599-000; PATH: I355; PHYS_PAGE: 16; ROT: 0; SEC: 1; SIGNAL_MODEL: nv_res; TOL: 5%; VER: 2; XY: (-10300,1850)
R267 = R#1: ASSEMBLY: GPIO_HDR; CDS_LIB: discrete; CDS_PART_NAME: R_0402-47K,5 %,62.5MW,195-0599-000; CDS_PHYS_PART_NAME: R_0402-47K,5 %,62.5MW,195-0599-000-195-0599-000,47K; CDS_SEC: 1; CHIPS_PART_NAME: R; DEVICE_TYPENAME: R_0402-47K5625MW195-0599-000-195-0599-00047K; DRAWING: @P2597_C02_LIB.P2597_C02(SCH_1):PAGE16; MAX_WATTAGE: 62.5mW; NV_PN: 195-0599-000; PATH: I344; PHYS_PAGE: 16; ROT: 0; SEC: 1; SIGNAL_MODEL: nv_res; TOL: 5%; VER: 2; XY: (-10050,1850)
R271 = R#1: ASSEMBLY: GPIO_HDR; CDS_LIB: discrete; CDS_PART_NAME: R_0402-47K,5 %,62.5MW,195-0599-000; CDS_PHYS_PART_NAME: R_0402-47K,5 %,62.5MW,195-0599-000-195-0599-000,47K; CDS_SEC: 1; CHIPS_PART_NAME: R; DEVICE_TYPENAME: R_0402-47K5625MW195-0599-000-195-0599-00047K; DRAWING: @P2597_C02_LIB.P2597_C02(SCH_1):PAGE16; MAX_WATTAGE: 62.5mW; NV_PN: 195-0599-000; PATH: I322; PHYS_PAGE: 16; ROT: 0; SEC: 1; SIGNAL_MODEL: nv_res; SKU: NO STUFF; TOL: 5%; VER: 2; XY: (-10600,1850)
R313 = R#1: ASSEMBLY: GPIO_HDR; CDS_LIB: discrete; CDS_PART_NAME: R_0402-0OHM,0.05 OHM,62.5MW,195-2655-000; CDS_PHYS_PART_NAME: R_0402-0OHM,0.05 OHM,62.5MW,195-2655-000-0OHM,195-2655-000; CDS_SEC: 1; CHIPS_PART_NAME: R; DEVICE_TYPENAME: R_0402-0OHM005OHM625MW195-2655-000-0OHM195-2655-000; DRAWING: @P2597_C02_LIB.P2597_C02(SCH_1):PAGE16; MAX_WATTAGE: 62.5mW; NV_PN: 195-2655-000; PATH: I411; PHYS_PAGE: 16; ROT: 0; SEC: 1; SIGNAL_MODEL: nv_res; SKU: NO STUFF; TOL: 0.05 ohm; VER: 2; XY: (-10100,950)
R326 = R#1: ASSEMBLY: GPIO_HDR; CDS_LIB: discrete; CDS_PART_NAME: R_0402-1M,5 %,62.5MW,195-0488-000; CDS_PHYS_PART_NAME: R_0402-1M,5 %,62.5MW,195-0488-000-195-0488-000,1M; CDS_SEC: 1; CHIPS_PART_NAME: R; DEVICE_TYPENAME: R_0402-1M5625MW195-0488-000-195-0488-0001M; DRAWING: @P2597_C02_LIB.P2597_C02(SCH_1):PAGE16; MAX_WATTAGE: 62.5mW; NV_PN: 195-0488-000; PATH: I413; PHYS_PAGE: 16; ROT: 0; SEC: 1; SIGNAL_MODEL: nv_res; TOL: 5%; VER: 2; XY: (-7950,3050)
R327 = R#1: ASSEMBLY: GPIO_HDR; CDS_LIB: discrete; CDS_PART_NAME: R_0402-1M,5 %,62.5MW,195-0488-000; CDS_PHYS_PART_NAME: R_0402-1M,5 %,62.5MW,195-0488-000-195-0488-000,1M; CDS_SEC: 1; CHIPS_PART_NAME: R; DEVICE_TYPENAME: R_0402-1M5625MW195-0488-000-195-0488-0001M; DRAWING: @P2597_C02_LIB.P2597_C02(SCH_1):PAGE16; MAX_WATTAGE: 62.5mW; NV_PN: 195-0488-000; PATH: I414; PHYS_PAGE: 16; ROT: 0; SEC: 1; SIGNAL_MODEL: nv_res; TOL: 5%; VER: 2; XY: (-7850,2800)
R328 = R#1: ASSEMBLY: GPIO_HDR; CDS_LIB: discrete; CDS_PART_NAME: R_0402-1M,5 %,62.5MW,195-0488-000; CDS_PHYS_PART_NAME: R_0402-1M,5 %,62.5MW,195-0488-000-195-0488-000,1M; CDS_SEC: 1; CHIPS_PART_NAME: R; DEVICE_TYPENAME: R_0402-1M5625MW195-0488-000-195-0488-0001M; DRAWING: @P2597_C02_LIB.P2597_C02(SCH_1):PAGE16; MAX_WATTAGE: 62.5mW; NV_PN: 195-0488-000; PATH: I415; PHYS_PAGE: 16; ROT: 0; SEC: 1; SIGNAL_MODEL: nv_res; TOL: 5%; VER: 2; XY: (-7700,3050)
R329 = R#1: ASSEMBLY: GPIO_HDR; CDS_LIB: discrete; CDS_PART_NAME: R_0402-1M,5 %,62.5MW,195-0488-000; CDS_PHYS_PART_NAME: R_0402-1M,5 %,62.5MW,195-0488-000-195-0488-000,1M; CDS_SEC: 1; CHIPS_PART_NAME: R; DEVICE_TYPENAME: R_0402-1M5625MW195-0488-000-195-0488-0001M; DRAWING: @P2597_C02_LIB.P2597_C02(SCH_1):PAGE16; MAX_WATTAGE: 62.5mW; NV_PN: 195-0488-000; PATH: I416; PHYS_PAGE: 16; ROT: 0; SEC: 1; SIGNAL_MODEL: nv_res; TOL: 5%; VER: 2; XY: (-7600,2800)
R330 = R#1: ASSEMBLY: GPIO_HDR; CDS_LIB: discrete; CDS_PART_NAME: R_0402-1M,5 %,62.5MW,195-0488-000; CDS_PHYS_PART_NAME: R_0402-1M,5 %,62.5MW,195-0488-000-195-0488-000,1M; CDS_SEC: 1; CHIPS_PART_NAME: R; DEVICE_TYPENAME: R_0402-1M5625MW195-0488-000-195-0488-0001M; DRAWING: @P2597_C02_LIB.P2597_C02(SCH_1):PAGE16; MAX_WATTAGE: 62.5mW; NV_PN: 195-0488-000; PATH: I420; PHYS_PAGE: 16; ROT: 0; SEC: 1; SIGNAL_MODEL: nv_res; TOL: 5%; VER: 2; XY: (-7450,3050)
R331 = R#1: ASSEMBLY: GPIO_HDR; CDS_LIB: discrete; CDS_PART_NAME: R_0402-1M,5 %,62.5MW,195-0488-000; CDS_PHYS_PART_NAME: R_0402-1M,5 %,62.5MW,195-0488-000-195-0488-000,1M; CDS_SEC: 1; CHIPS_PART_NAME: R; DEVICE_TYPENAME: R_0402-1M5625MW195-0488-000-195-0488-0001M; DRAWING: @P2597_C02_LIB.P2597_C02(SCH_1):PAGE16; MAX_WATTAGE: 62.5mW; NV_PN: 195-0488-000; PATH: I419; PHYS_PAGE: 16; ROT: 0; SEC: 1; SIGNAL_MODEL: nv_res; TOL: 5%; VER: 2; XY: (-7350,2800)
R332 = R#1: ASSEMBLY: GPIO_HDR; CDS_LIB: discrete; CDS_PART_NAME: R_0402-1M,5 %,62.5MW,195-0488-000; CDS_PHYS_PART_NAME: R_0402-1M,5 %,62.5MW,195-0488-000-195-0488-000,1M; CDS_SEC: 1; CHIPS_PART_NAME: R; DEVICE_TYPENAME: R_0402-1M5625MW195-0488-000-195-0488-0001M; DRAWING: @P2597_C02_LIB.P2597_C02(SCH_1):PAGE16; MAX_WATTAGE: 62.5mW; NV_PN: 195-0488-000; PATH: I418; PHYS_PAGE: 16; ROT: 0; SEC: 1; SIGNAL_MODEL: nv_res; TOL: 5%; VER: 2; XY: (-7200,3050)
R333 = R#1: ASSEMBLY: GPIO_HDR; CDS_LIB: discrete; CDS_PART_NAME: R_0402-1M,5 %,62.5MW,195-0488-000; CDS_PHYS_PART_NAME: R_0402-1M,5 %,62.5MW,195-0488-000-195-0488-000,1M; CDS_SEC: 1; CHIPS_PART_NAME: R; DEVICE_TYPENAME: R_0402-1M5625MW195-0488-000-195-0488-0001M; DRAWING: @P2597_C02_LIB.P2597_C02(SCH_1):PAGE16; MAX_WATTAGE: 62.5mW; NV_PN: 195-0488-000; PATH: I417; PHYS_PAGE: 16; ROT: 0; SEC: 1; SIGNAL_MODEL: nv_res; TOL: 5%; VER: 2; XY: (-7100,2800)
R334 = R#1: ASSEMBLY: GPIO_HDR; CDS_LIB: discrete; CDS_PART_NAME: R_0402-1M,5 %,62.5MW,195-0488-000; CDS_PHYS_PART_NAME: R_0402-1M,5 %,62.5MW,195-0488-000-195-0488-000,1M; CDS_SEC: 1; CHIPS_PART_NAME: R; DEVICE_TYPENAME: R_0402-1M5625MW195-0488-000-195-0488-0001M; DRAWING: @P2597_C02_LIB.P2597_C02(SCH_1):PAGE16; MAX_WATTAGE: 62.5mW; NV_PN: 195-0488-000; PATH: I452; PHYS_PAGE: 16; ROT: 0; SEC: 1; SIGNAL_MODEL: nv_res; TOL: 5%; VER: 2; XY: (-2450,3000)
R335 = R#1: ASSEMBLY: GPIO_HDR; CDS_LIB: discrete; CDS_PART_NAME: R_0402-1M,5 %,62.5MW,195-0488-000; CDS_PHYS_PART_NAME: R_0402-1M,5 %,62.5MW,195-0488-000-195-0488-000,1M; CDS_SEC: 1; CHIPS_PART_NAME: R; DEVICE_TYPENAME: R_0402-1M5625MW195-0488-000-195-0488-0001M; DRAWING: @P2597_C02_LIB.P2597_C02(SCH_1):PAGE16; MAX_WATTAGE: 62.5mW; NV_PN: 195-0488-000; PATH: I451; PHYS_PAGE: 16; ROT: 0; SEC: 1; SIGNAL_MODEL: nv_res; TOL: 5%; VER: 2; XY: (-2350,2750)
R336 = R#1: ASSEMBLY: GPIO_HDR; CDS_LIB: discrete; CDS_PART_NAME: R_0402-1M,5 %,62.5MW,195-0488-000; CDS_PHYS_PART_NAME: R_0402-1M,5 %,62.5MW,195-0488-000-195-0488-000,1M; CDS_SEC: 1; CHIPS_PART_NAME: R; DEVICE_TYPENAME: R_0402-1M5625MW195-0488-000-195-0488-0001M; DRAWING: @P2597_C02_LIB.P2597_C02(SCH_1):PAGE16; MAX_WATTAGE: 62.5mW; NV_PN: 195-0488-000; PATH: I450; PHYS_PAGE: 16; ROT: 0; SEC: 1; SIGNAL_MODEL: nv_res; TOL: 5%; VER: 2; XY: (-2200,3000)
R337 = R#1: ASSEMBLY: GPIO_HDR; CDS_LIB: discrete; CDS_PART_NAME: R_0402-1M,5 %,62.5MW,195-0488-000; CDS_PHYS_PART_NAME: R_0402-1M,5 %,62.5MW,195-0488-000-195-0488-000,1M; CDS_SEC: 1; CHIPS_PART_NAME: R; DEVICE_TYPENAME: R_0402-1M5625MW195-0488-000-195-0488-0001M; DRAWING: @P2597_C02_LIB.P2597_C02(SCH_1):PAGE16; MAX_WATTAGE: 62.5mW; NV_PN: 195-0488-000; PATH: I449; PHYS_PAGE: 16; ROT: 0; SEC: 1; SIGNAL_MODEL: nv_res; TOL: 5%; VER: 2; XY: (-2100,2750)
R339 = R#1: ASSEMBLY: GPIO_HDR; CDS_LIB: discrete; CDS_PART_NAME: R_0402-1M,5 %,62.5MW,195-0488-000; CDS_PHYS_PART_NAME: R_0402-1M,5 %,62.5MW,195-0488-000-195-0488-000,1M; CDS_SEC: 1; CHIPS_PART_NAME: R; DEVICE_TYPENAME: R_0402-1M5625MW195-0488-000-195-0488-0001M; DRAWING: @P2597_C02_LIB.P2597_C02(SCH_1):PAGE16; MAX_WATTAGE: 62.5mW; NV_PN: 195-0488-000; PATH: I447; PHYS_PAGE: 16; ROT: 0; SEC: 1; SIGNAL_MODEL: nv_res; TOL: 5%; VER: 2; XY: (-1850,2750)
R340 = R#1: ASSEMBLY: GPIO_HDR; CDS_LIB: discrete; CDS_PART_NAME: R_0402-1M,5 %,62.5MW,195-0488-000; CDS_PHYS_PART_NAME: R_0402-1M,5 %,62.5MW,195-0488-000-195-0488-000,1M; CDS_SEC: 1; CHIPS_PART_NAME: R; DEVICE_TYPENAME: R_0402-1M5625MW195-0488-000-195-0488-0001M; DRAWING: @P2597_C02_LIB.P2597_C02(SCH_1):PAGE16; MAX_WATTAGE: 62.5mW; NV_PN: 195-0488-000; PATH: I446; PHYS_PAGE: 16; ROT: 0; SEC: 1; SIGNAL_MODEL: nv_res; TOL: 5%; VER: 2; XY: (-1700,3000)
R341 = R#1: ASSEMBLY: GPIO_HDR; CDS_LIB: discrete; CDS_PART_NAME: R_0402-1M,5 %,62.5MW,195-0488-000; CDS_PHYS_PART_NAME: R_0402-1M,5 %,62.5MW,195-0488-000-195-0488-000,1M; CDS_SEC: 1; CHIPS_PART_NAME: R; DEVICE_TYPENAME: R_0402-1M5625MW195-0488-000-195-0488-0001M; DRAWING: @P2597_C02_LIB.P2597_C02(SCH_1):PAGE16; MAX_WATTAGE: 62.5mW; NV_PN: 195-0488-000; PATH: I445; PHYS_PAGE: 16; ROT: 0; SEC: 1; SIGNAL_MODEL: nv_res; TOL: 5%; VER: 2; XY: (-1600,2750)
R342 = R: ASSEMBLY: GPIO_HDR; CDS_LIB: discrete; CDS_PART_NAME: R_0402-0OHM,0.05 OHM,62.5MW,195-2655-000; CDS_PHYS_PART_NAME: R_0402-0OHM,0.05 OHM,62.5MW,195-2655-000-0OHM,195-2655-000; CDS_SEC: 1; DEVICE_TYPENAME: R_0402-0OHM005OHM625MW195-2655-000-0OHM195-2655-000; DRAWING: @P2597_C02_LIB.P2597_C02(SCH_1):PAGE16; MAX_WATTAGE: 62.5mW; NV_PN: 195-2655-000; PATH: I453; PHYS_PAGE: 16; ROT: 0; SEC: 1; SIGNAL_MODEL: nv_res; TOL: 0.05 ohm; VER: 1; XY: (-4050,2800)
R343 = R: ASSEMBLY: GPIO_HDR; CDS_LIB: discrete; CDS_PART_NAME: R_0402-0OHM,0.05 OHM,62.5MW,195-2655-000; CDS_PHYS_PART_NAME: R_0402-0OHM,0.05 OHM,62.5MW,195-2655-000-0OHM,195-2655-000; CDS_SEC: 1; DEVICE_TYPENAME: R_0402-0OHM005OHM625MW195-2655-000-0OHM195-2655-000; DRAWING: @P2597_C02_LIB.P2597_C02(SCH_1):PAGE16; MAX_WATTAGE: 62.5mW; NV_PN: 195-2655-000; PATH: I454; PHYS_PAGE: 16; ROT: 0; SEC: 1; SIGNAL_MODEL: nv_res; TOL: 0.05 ohm; VER: 1; XY: (-9750,2800)
R344 = R#1: ASSEMBLY: GPIO_HDR; CDS_LIB: discrete; CDS_PART_NAME: R_0402-1M,5 %,62.5MW,195-0488-000; CDS_PHYS_PART_NAME: R_0402-1M,5 %,62.5MW,195-0488-000-195-0488-000,1M; CDS_SEC: 1; CHIPS_PART_NAME: R; DEVICE_TYPENAME: R_0402-1M5625MW195-0488-000-195-0488-0001M; DRAWING: @P2597_C02_LIB.P2597_C02(SCH_1):PAGE16; MAX_WATTAGE: 62.5mW; NV_PN: 195-0488-000; PATH: I458; PHYS_PAGE: 16; ROT: 2; SEC: 1; SIGNAL_MODEL: nv_res; TOL: 5%; VER: 2; XY: (-4900,5050)
R345 = R#1: ASSEMBLY: GPIO_HDR; CDS_LIB: discrete; CDS_PART_NAME: R_0402-1M,5 %,62.5MW,195-0488-000; CDS_PHYS_PART_NAME: R_0402-1M,5 %,62.5MW,195-0488-000-195-0488-000,1M; CDS_SEC: 1; CHIPS_PART_NAME: R; DEVICE_TYPENAME: R_0402-1M5625MW195-0488-000-195-0488-0001M; DRAWING: @P2597_C02_LIB.P2597_C02(SCH_1):PAGE16; MAX_WATTAGE: 62.5mW; NV_PN: 195-0488-000; PATH: I457; PHYS_PAGE: 16; ROT: 0; SEC: 1; SIGNAL_MODEL: nv_res; TOL: 5%; VER: 2; XY: (-3650,5000)
R517 = R: ASSEMBLY: GPIO_HDR; CDS_LIB: discrete; CDS_PART_NAME: R_0402-0OHM,0.05 OHM,62.5MW,195-2655-000; CDS_PHYS_PART_NAME: R_0402-0OHM,0.05 OHM,62.5MW,195-2655-000-0OHM,195-2655-000; CDS_SEC: 1; DEVICE_TYPENAME: R_0402-0OHM005OHM625MW195-2655-000-0OHM195-2655-000; DRAWING: @P2597_C02_LIB.P2597_C02(SCH_1):PAGE16; MAX_WATTAGE: 62.5mW; NO_XNET_CONNECTION: 1; NV_PN: 195-2655-000; PATH: I365; PHYS_PAGE: 16; ROT: 0; SEC: 1; SIGNAL_MODEL: nv_res; SKU: NO STUFF; TOL: 0.05 ohm; VER: 1; XY: (-8500,4100)
R585 = R: ASSEMBLY: GPIO_HDR; CDS_LIB: discrete; CDS_PART_NAME: R_0402-0OHM,0.05 OHM,62.5MW,195-2655-000; CDS_PHYS_PART_NAME: R_0402-0OHM,0.05 OHM,62.5MW,195-2655-000-0OHM,195-2655-000; CDS_SEC: 1; DEVICE_TYPENAME: R_0402-0OHM005OHM625MW195-2655-000-0OHM195-2655-000; DRAWING: @P2597_C02_LIB.P2597_C02(SCH_1):PAGE16; MAX_WATTAGE: 62.5mW; NO_XNET_CONNECTION: 1; NV_PN: 195-2655-000; PATH: I357; PHYS_PAGE: 16; ROT: 0; SEC: 1; SIGNAL_MODEL: nv_res; SKU: NO STUFF; TOL: 0.05 ohm; VER: 1; XY: (-9700,4700)
R592 = R: ASSEMBLY: GPIO_HDR; CDS_LIB: discrete; CDS_PART_NAME: R_0402-0OHM,0.05 OHM,62.5MW,195-2655-000; CDS_PHYS_PART_NAME: R_0402-0OHM,0.05 OHM,62.5MW,195-2655-000-0OHM,195-2655-000; CDS_SEC: 1; DEVICE_TYPENAME: R_0402-0OHM005OHM625MW195-2655-000-0OHM195-2655-000; DRAWING: @P2597_C02_LIB.P2597_C02(SCH_1):PAGE16; MAX_WATTAGE: 62.5mW; NO_XNET_CONNECTION: 1; NV_PN: 195-2655-000; PATH: I366; PHYS_PAGE: 16; ROT: 0; SEC: 1; SIGNAL_MODEL: nv_res; SKU: NO STUFF; TOL: 0.05 ohm; VER: 1; XY: (-3150,4100)
R3238 = R#1: ASSEMBLY: GPIO_HDR; CDS_LIB: discrete; CDS_PART_NAME: R_0402-1M,5 %,62.5MW,195-0488-000; CDS_PHYS_PART_NAME: R_0402-1M,5 %,62.5MW,195-0488-000-195-0488-000,1M; CDS_SEC: 1; CHIPS_PART_NAME: R; DEVICE_TYPENAME: R_0402-1M5625MW195-0488-000-195-0488-0001M; DRAWING: @P2597_C02_LIB.P2597_C02(SCH_1):PAGE16; MAX_WATTAGE: 62.5mW; NV_PN: 195-0488-000; PATH: I448; PHYS_PAGE: 16; ROT: 0; SEC: 1; SIGNAL_MODEL: nv_res; TOL: 5%; VER: 2; XY: (-1950,3000)
U7 = U_LEVSHFT_TXB0108: ASSEMBLY: GPIO_HDR; CDS_LIB: digital; CDS_PART_NAME: U_LEVSHFT_TXB0108_QFN20-TXB0108RGYR,LEVEL SHIFTER,115-1921-000; CDS_PHYS_PART_NAME: U_LEVSHFT_TXB0108_QFN20-TXB0108RGYR,LEVEL SHIFTER,115-1921-000-115-1921-000; CDS_SEC: 1; DEVICE_TYPENAME: U_LEVSHFT_TXB0108_QFN20-TXB0108RGYRLEVELSHIFTER115-1921-000-115-1921-000; DRAWING: @P2597_C02_LIB.P2597_C02(SCH_1):PAGE16; FUNCTION: Level Shifter; NV_NAME: TXB0108RGYR; NV_PN: 115-1921-000; PACK_TYPE: QFN20; PATH: I183; PHYS_PAGE: 16; ROT: 0; SEC: 1; SEC_TYPE: QFN20; VER: 1; XY: (-3100,3400)
U22 = U_LEVSHFT_TXB0108: ASSEMBLY: GPIO_HDR; CDS_LIB: digital; CDS_PART_NAME: U_LEVSHFT_TXB0108_QFN20-TXB0108RGYR,LEVEL SHIFTER,115-1921-000; CDS_PHYS_PART_NAME: U_LEVSHFT_TXB0108_QFN20-TXB0108RGYR,LEVEL SHIFTER,115-1921-000-115-1921-000; CDS_SEC: 1; DEVICE_TYPENAME: U_LEVSHFT_TXB0108_QFN20-TXB0108RGYRLEVELSHIFTER115-1921-000-115-1921-000; DRAWING: @P2597_C02_LIB.P2597_C02(SCH_1):PAGE16; FUNCTION: Level Shifter; NV_NAME: TXB0108RGYR; NV_PN: 115-1921-000; PACK_TYPE: QFN20; PATH: I182; PHYS_PAGE: 16; ROT: 0; SEC: 1; SEC_TYPE: QFN20; VER: 1; XY: (-8500,3400)

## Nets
3V3_GPIO_HDR: C92.1 F1.2 J21.1 J21.17
5V0_GPIO_HDR: C101.1 F2.1 J21.2 J21.4
GND: C55.2 C56.2 C92.2 C101.2 C136.2 C137.2 C175.2 C180.2 C181.2 D22.2(GND) D23.2(GND) D24.2(GND) D25.2(GND) D26.2(GND) D27.2(2A) D28.2(2A) D29.2(2A) D32.2(2A) D33.2(2A) D34.2(GND) J21.6 J21.9 J21.14 J21.20 J21.25 J21.30 J21.34 J21.39 J26.10 J26.11 J26.21 J26.28 J27.4 J27.11(MNT1) J27.12(MNT2) R72.1 R203.1 R313.2 R326.2 R327.2 R328.2 R329.2 R330.2 R331.2 R332.2 R333.2 R334.2 R335.2 R336.2 R337.2 R339.2 R340.2 R341.2 R344.2 R345.2 R3238.2 U7.11(GND) U7.21(EP) U22.11(GND) U22.21(EP) ; also on sheet 1 2 3 4 5 6 7 9 10 11 12 13 14 15 16 17 19 20 21 22 23 24 25 26 30
VDD_1V8: C55.1 C136.1 F4.1 J24.3 Q27.1(G) Q28.1(G) R70.1 R204.1 R257.1 R263.1 R266.1 R271.1 R517.1 R592.1 U7.2(VCCA) U22.2(VCCA) ; also on sheet 4 5 9 10 12 13 16 17 19 20 22 24 30
VDD_3V3_SYS: F1.1 F3.1 J24.1 R261.1 R262.1 R267.1 ; also on sheet 1 2 3 4 5 6 12 13 17 19 23 24 25
VDD_5V0_IO_SYS: F2.2 F5.1 ; also on sheet 4 5 6 9 11 12 16 17 20 22 26 30
VDD_GPIO_TXL8: J24.2 R100.2 R223.2
VDD_GPIO_TXL81: C137.1 R223.1 R517.2 U22.19(VCCB)
VDD_GPIO_TXL82: C56.1 R100.1 R592.2 U7.19(VCCB)
ACOK: J27.1 R271.2 R313.1 ; also on sheet 12 17 30
AO_DMIC_IN_CLK: U7.8(A7) ; also on sheet 16 30
AO_DMIC_IN_CLK_LVL: J21.32 R340.1 U7.13(B7)
AO_DMIC_IN_DAT: U7.9(A8) ; also on sheet 16 30
AO_DMIC_IN_DAT_LVL: J21.16 R341.1 U7.12(B8)
AP2MDM_READY: D23.5(LINE4) J26.6 ; also on sheet 28
AP_WAKE_BT: U7.7(A6) ; also on sheet 28
AP_WAKE_BT_3V3: J21.33 R339.1 U7.14(B6)
AUD_RST: U22.9(A8) ; also on sheet 30
AUD_RST_LVL: J21.29 R333.1 U22.12(B8)
AUDIO_CDC_IRQ: U22.7(A6) ; also on sheet 30
AUDIO_CDC_IRQ_LVL: J21.13 R331.1 U22.14(B6)
AUDIO_I2S_MCLK: U22.1(A1) ; also on sheet 30
AUDIO_I2S_MCLK_3V3: J21.7 R326.1 U22.20(B1)
AUDIO_I2S_SFSYNC: U22.3(A2) ; also on sheet 30
AUDIO_I2S_SFSYNC_3V3: J21.35 R327.1 U22.18(B2)
AUDIO_I2S_SIN: U22.5(A4) ; also on sheet 30
AUDIO_I2S_SIN_3V3: J21.38 R329.1 U22.16(B4)
AUDIO_I2S_SOUT: U22.4(A3) ; also on sheet 30
AUDIO_I2S_SOUT_3V3: J21.40 R328.1 U22.17(B3)
AUDIO_I2S_SRCLK: U22.6(A5) ; also on sheet 30
AUDIO_I2S_SRCLK_3V3: J21.12 R330.1 U22.15(B5)
BAT_DET_L: J27.8 R267.2
CAN0_ERR: D26.4(LINE3) J26.9 ; also on sheet 28
CAN0_RX: D26.5(LINE4) J26.5 ; also on sheet 28
CAN0_STBY: D26.1(LINE1) J26.3 ; also on sheet 28
CAN0_TX: D25.3(LINE2) J26.7 ; also on sheet 28
CAN1_ERR: D25.1(LINE1) J26.19 ; also on sheet 28
CAN1_RX: D25.5(LINE4) J26.15 ; also on sheet 28
CAN1_STBY: D22.3(LINE2) J26.13 ; also on sheet 28
CAN1_TX: D25.4(LINE3) J26.17 ; also on sheet 28
CAN_WAKE: D26.3(LINE2) J26.1 ; also on sheet 28
CHARGING: D34.5(LINE4) J27.2 ; also on sheet 30
CHG_BD_PRSNT_L: J27.10 R266.2 ; also on sheet 13
CHG_OC_L: J27.7 ; also on sheet 24 30
DSPK_OUT_CLK: D29.1(1C) J26.27 ; also on sheet 30
DSPK_OUT_DAT: D28.1(1C) J26.29 ; also on sheet 30
GNSS_PPS: D27.1(1C) J26.30 ; also on sheet 28
GPIO_EXP_P16_3V3: J21.22 R345.1 ; also on sheet 13
GPIO_EXP_P17_3V3: J21.15 R344.1 ; also on sheet 13
I2C_GP0_SCL_3V3_LVL: J21.5 ; also on sheet 24 25
I2C_GP0_SDA_3V3_LVL: J21.3 ; also on sheet 24 25
I2C_GP1_CLK_3V3: D33.1(1C) J21.28 ; also on sheet 2 3 12 13 17 19 30
I2C_GP1_DAT_3V3: D32.1(1C) J21.27 ; also on sheet 2 3 12 13 17 19 30
I2C_GP2_CLK: D23.3(LINE2) J26.12 ; also on sheet 30
I2C_GP2_DAT: D24.5(LINE4) J26.14 ; also on sheet 30
I2C_GP3_CLK: D24.4(LINE3) J26.18 ; also on sheet 30
I2C_GP3_DAT: D24.1(LINE1) J26.20 ; also on sheet 30
I2C_PM_CLK: D34.3(LINE2) J27.5 ; also on sheet 10 12 16 30
I2C_PM_DAT: D34.1(LINE1) J27.6 ; also on sheet 10 12 16 30
I2S1_CLK: D22.1(LINE1) J26.23 ; also on sheet 28
I2S1_LRCLK: D24.3(LINE2) J26.26 ; also on sheet 28
I2S1_SDIN: D22.5(LINE4) J26.25 R585.2 ; also on sheet 28
I2S1_SDOUT: D22.4(LINE3) J26.24 ; also on sheet 28
LOW_BAT: D34.4(LINE3) J27.3 ; also on sheet 30
MDM_WAKE_AP_1V8: U22.8(A7) ; also on sheet 24 28
MDM_WAKE_AP_LVL: J21.18 R332.1 U22.13(B7)
MOTION_INT_AP_L: Q28.2(S) R263.2 ; also on sheet 16 30
MOTION_INT_AP_L_LVL: J21.31 Q28.3(D) R262.2
P_P2_3V3: C181.1 F3.2 J26.2
P_P6_1V8: C180.1 F4.2 J26.4
P_P8_5V: C175.1 F5.2 J26.8
RESET_OUT_L: D16.1(C) ; also on sheet 5 9 12 30
SAR_CTRL: R585.1 ; also on sheet 24
SAR_TOUT: Q27.2(S) R257.2 ; also on sheet 24 30
SAR_TOUT_LVL: J21.37 Q27.3(D) R261.2
SLEEP: D23.1(LINE1) J26.22 ; also on sheet 1 30
SPI1_CS0: U7.5(A4) ; also on sheet 30
SPI1_CS0_3V3: J21.24 R337.1 U7.16(B4)
SPI1_CS1: U7.6(A5) ; also on sheet 30
SPI1_CS1_3V3: J21.26 R3238.1 U7.15(B5)
SPI1_MISO: U7.3(A2) ; also on sheet 30
SPI1_MISO_3V3: J21.21 R335.1 U7.18(B2)
SPI1_MOSI: U7.1(A1) ; also on sheet 30
SPI1_MOSI_3V3: J21.19 R334.1 U7.20(B1)
SPI1_SCK: U7.4(A3) ; also on sheet 30
SPI1_SCK_3V3: J21.23 R336.1 U7.17(B3)
TXL8_1_OE: R203.2 R204.2 R343.2 U22.10(OE)
TXL8_2_OE: R70.2 R72.2 R342.2 U7.10(OE)
TXL8_OE: D16.2(A) R342.1 R343.1
TYPEC_INT: J27.9 ; also on sheet 13
UART1_CTS_HDR_3V3: J21.36 ; also on sheet 19
UART1_RTS_HDR_3V3: J21.11 ; also on sheet 19
UART1_RXD_HDR_3V3: J21.10 ; also on sheet 19
UART1_TXD_HDR_3V3: J21.8 ; also on sheet 19
WDT_TIME_OUT_L: D23.4(LINE3) J26.16 ; also on sheet 30

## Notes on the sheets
sheet 18
- A
- B
- C
- D
- E
- F
- G
- H
- GPIO Expansion Headers
- 1
- 1
- 2
- 2
- KEEP RESISTOR NEAR
- HEADER TO MINIMIZE STUB
- NS
- NS
- 3
- 3
- GPIO_PK0 I2S5B_FS
- GPIO_PK2 I2S5B_SDOUT
- GPIO_PK1 I2S5B_SDIN
- 4
- 4
- CHARGER
- CONTROL HDR
- NS
- CAD NOTE:
- Place near a board edge
- NS
- 5
- 5
- NVIDIA CORPORATION
- 2701 SAN TOMAS EXPRESSWAY
- ASSEMBLY
- <ASSEMBLY_DESCRIPTION>
- SANTA CLARA, CA 95050, USA
- PAGE DETAIL
- IO Expansion Connector
- NV_PN
- 600-82597-BASE-900
- ALL NVIDIA DESIGN SPECIFICATIONS, REFERENCE SPECIFICATIONS, REFERENCE BOARDS, FILES, DRAWINGS, DIAGNOSTICS, LISTS AND OTHER DOCUMENTS OR INFORMATION (TOGETHER AND SEPARATELY, 'MATERIALS') ARE BEING PROVIDED 'AS IS'. THE MATERIALS MAY
- CONTAIN KNOWN AND UNKNOWN VIOLATIONS OR DEVIATIONS OF INDUSTRY STANDARDS AND SPECIFICATIONS. NVIDIA MAKES NO WARRANTIES, EXPRESSED, IMPLIED, STATUTORY OR OTHERWISE WITH RESPECT TO THE MATERIALS OR OTHERWISE, AND EXPRESSLY DISCLAIMS ALL
- PCB REV
- P2597-C02
- PAGE
- 16 OF 34
- IMPLIED WARRANTIES INCLUDING, WITHOUT LIMITATION, THE WARRANTIES OF DESIGN, OF NONINFRINGEMENT, MERCHANTABILITY OR FITNESS FOR A PARTICULAR PURPOSE, OR ARISING FROM A COURSE OF DEALING, TRADE USAGE, TRADE PRACTICE, OR INDUSTRY STANDARDS.
- BOM REV
- A
- DATE
- 23-OCT-2017
- A
- B
- C
- D
- E
- F
- G
- H
